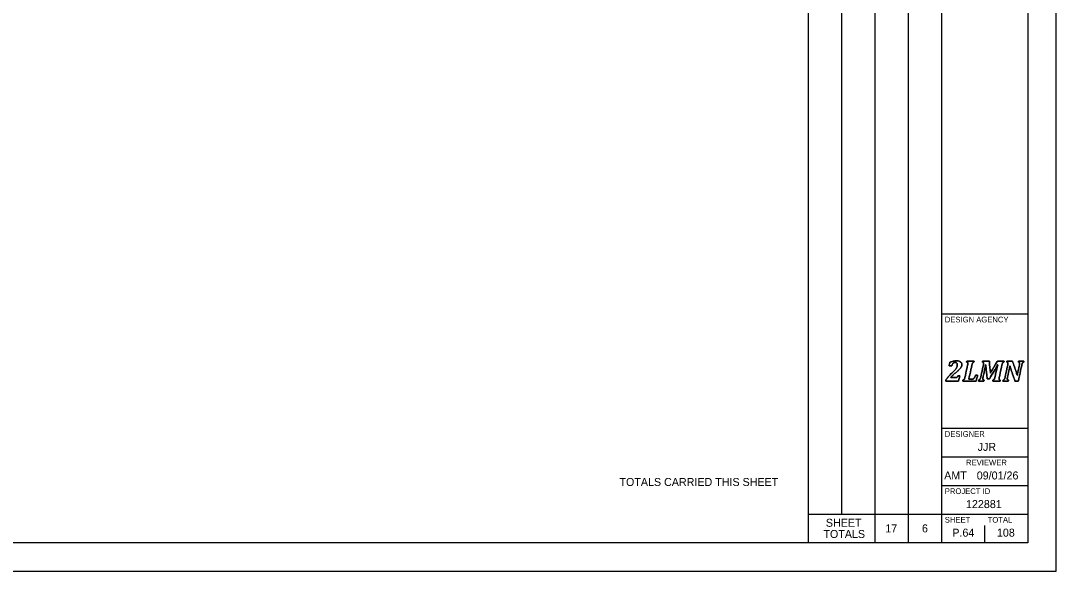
# Model space of a CAD drawing. Extents: x -32 to 34, y 0 to 22.
# Drawn here: x 15.89 to 34, y 0 to 9.62 of the extents above; entities that cross this region are included whole.
import ezdxf

# ---------------------------------------------------------------- set-up
doc = ezdxf.new("R2010")
doc.units = 0
for name, color, linetype in [('SH_Border', 7, 'Continuous'), ('SH_Cut_Line', 7, 'Continuous'), ('SH_Data', 7, 'Continuous'), ('SH_Major_Grid_Line', 7, 'Continuous'), ('SH_Text', 7, 'Continuous')]:
    doc.layers.add(name, color=color, linetype=linetype)

msp = doc.modelspace()

# ---------------------------------------------------------------- linework, layer by layer
at = {"layer": 'SH_Border'}
for p, q in [((32, 0.5), (32, 21.5)), ((32, 4.5), (33.5, 4.5)), ((32, 2.5), (33.5, 2.5)), ((32, 2), (33.5, 2)), ((32, 1.5), (33.5, 1.5)), ((32, 1), (33.5, 1))]:
    msp.add_line(p, q, dxfattribs=at)
msp.add_lwpolyline([(1.5, 21.5), (33.5, 21.5), (33.5, 0.5), (1.5, 0.5)], close=True, dxfattribs=at)
at = {"layer": 'SH_Cut_Line'}
msp.add_lwpolyline([(0, 0), (34, 0), (34, 22), (0, 22)], close=True, dxfattribs=at)
at = {"layer": 'SH_Data'}
for p, q in [((29.666, 0.5), (29.666, 21.5)), ((30.833, 0.5), (30.833, 21.5)), ((30.25, 1), (30.25, 21.25)), ((31.417, 0.5), (31.417, 21.25)), ((32.75, 3.5), (32.75, 3.5)), ((29.666, 1), (32, 1)), ((29.958, 0.75), (29.958, 0.75)), ((30.542, 0.75), (30.542, 0.75)), ((31.125, 0.75), (31.125, 0.75)), ((31.708, 0.75), (31.708, 0.75)), ((32.75, 0.5), (32.75, 0.8)), ((32.375, 0.675), (32.375, 0.675))]:
    msp.add_line(p, q, dxfattribs=at)
for points in [[(32.237, 3.388), (32.246, 3.388), (32.253, 3.389), (32.258, 3.39), (32.263, 3.392), (32.267, 3.394), (32.27, 3.397), (32.273, 3.401), (32.277, 3.408), (32.281, 3.417), (32.281, 3.417), (32.312, 3.417), (32.312, 3.417), (32.312, 3.417), (32.29, 3.326), (32.29, 3.326), (32.29, 3.326), (32.066, 3.326), (32.066, 3.326), (32.066, 3.326), (32.069, 3.343), (32.069, 3.343), (32.078, 3.358), (32.091, 3.375), (32.106, 3.394), (32.122, 3.412), (32.144, 3.435), (32.172, 3.462), (32.197, 3.486), (32.217, 3.506), (32.23, 3.521), (32.243, 3.537), (32.253, 3.551), (32.259, 3.566), (32.266, 3.58), (32.269, 3.595), (32.269, 3.61), (32.269, 3.622), (32.266, 3.632), (32.26, 3.64), (32.253, 3.647), (32.245, 3.65), (32.234, 3.65), (32.22, 3.65), (32.208, 3.646), (32.198, 3.636), (32.188, 3.627), (32.18, 3.613), (32.172, 3.593), (32.172, 3.593), (32.126, 3.593), (32.126, 3.593), (32.126, 3.593), (32.14, 3.654), (32.14, 3.654), (32.166, 3.663), (32.188, 3.669), (32.205, 3.673), (32.223, 3.676), (32.24, 3.678), (32.258, 3.678), (32.278, 3.678), (32.295, 3.675), (32.309, 3.669), (32.322, 3.664), (32.332, 3.656), (32.339, 3.646), (32.345, 3.637), (32.348, 3.626), (32.348, 3.613), (32.348, 3.602), (32.346, 3.591), (32.342, 3.581), (32.339, 3.571), (32.333, 3.56), (32.324, 3.549), (32.315, 3.539), (32.304, 3.526), (32.289, 3.513), (32.275, 3.499), (32.254, 3.482), (32.228, 3.46), (32.216, 3.45), (32.202, 3.438), (32.188, 3.425), (32.174, 3.412), (32.162, 3.4), (32.154, 3.391), (32.154, 3.391), (32.153, 3.388), (32.153, 3.388), (32.153, 3.388), (32.237, 3.388), (32.237, 3.388)], [(32.237, 3.388), (32.237, 3.388), (32.153, 3.388), (32.153, 3.388), (32.153, 3.388), (32.154, 3.391), (32.154, 3.391), (32.162, 3.4), (32.174, 3.412), (32.188, 3.425), (32.202, 3.438), (32.216, 3.45), (32.228, 3.46), (32.254, 3.482), (32.275, 3.499), (32.289, 3.513), (32.304, 3.526), (32.315, 3.539), (32.324, 3.549), (32.333, 3.56), (32.339, 3.571), (32.342, 3.581), (32.346, 3.591), (32.348, 3.602), (32.348, 3.613), (32.348, 3.626), (32.345, 3.637), (32.339, 3.646), (32.332, 3.656), (32.322, 3.664), (32.309, 3.669), (32.295, 3.675), (32.278, 3.678), (32.258, 3.678), (32.24, 3.678), (32.223, 3.676), (32.205, 3.673), (32.188, 3.669), (32.166, 3.663), (32.14, 3.654), (32.14, 3.654), (32.126, 3.593), (32.126, 3.593), (32.126, 3.593), (32.172, 3.593), (32.172, 3.593), (32.18, 3.613), (32.188, 3.627), (32.198, 3.636), (32.208, 3.646), (32.22, 3.65), (32.234, 3.65), (32.245, 3.65), (32.253, 3.647), (32.26, 3.64), (32.266, 3.632), (32.269, 3.622), (32.269, 3.61), (32.269, 3.595), (32.266, 3.58), (32.259, 3.566), (32.253, 3.551), (32.243, 3.537), (32.23, 3.521), (32.217, 3.506), (32.197, 3.486), (32.172, 3.462), (32.144, 3.435), (32.122, 3.412), (32.106, 3.394), (32.091, 3.375), (32.078, 3.358), (32.069, 3.343), (32.069, 3.343), (32.066, 3.326), (32.066, 3.326), (32.066, 3.326), (32.29, 3.326), (32.29, 3.326), (32.29, 3.326), (32.312, 3.417), (32.312, 3.417), (32.312, 3.417), (32.281, 3.417), (32.281, 3.417), (32.277, 3.408), (32.273, 3.401), (32.27, 3.397), (32.267, 3.394), (32.263, 3.392), (32.258, 3.39), (32.253, 3.389), (32.246, 3.388), (32.237, 3.388)], [(32.518, 3.356), (32.527, 3.356), (32.533, 3.357), (32.538, 3.358), (32.542, 3.36), (32.546, 3.362), (32.55, 3.365), (32.554, 3.368), (32.558, 3.372), (32.562, 3.377), (32.567, 3.382), (32.571, 3.388), (32.576, 3.397), (32.58, 3.405), (32.585, 3.415), (32.589, 3.427), (32.589, 3.427), (32.624, 3.427), (32.624, 3.427), (32.624, 3.427), (32.598, 3.326), (32.598, 3.326), (32.598, 3.326), (32.365, 3.326), (32.365, 3.326), (32.365, 3.326), (32.369, 3.343), (32.369, 3.343), (32.376, 3.345), (32.381, 3.348), (32.385, 3.351), (32.389, 3.355), (32.392, 3.36), (32.395, 3.366), (32.398, 3.373), (32.4, 3.382), (32.403, 3.395), (32.403, 3.395), (32.449, 3.605), (32.449, 3.605), (32.452, 3.615), (32.453, 3.625), (32.453, 3.635), (32.453, 3.642), (32.451, 3.647), (32.448, 3.651), (32.444, 3.654), (32.439, 3.656), (32.432, 3.657), (32.432, 3.657), (32.435, 3.674), (32.435, 3.674), (32.435, 3.674), (32.563, 3.674), (32.563, 3.674), (32.563, 3.674), (32.559, 3.657), (32.559, 3.657), (32.552, 3.655), (32.547, 3.652), (32.543, 3.649), (32.539, 3.645), (32.536, 3.64), (32.533, 3.634), (32.531, 3.627), (32.528, 3.618), (32.525, 3.605), (32.525, 3.605), (32.47, 3.356), (32.47, 3.356), (32.47, 3.356), (32.518, 3.356), (32.518, 3.356)], [(32.518, 3.356), (32.518, 3.356), (32.47, 3.356), (32.47, 3.356), (32.47, 3.356), (32.525, 3.605), (32.525, 3.605), (32.528, 3.618), (32.531, 3.627), (32.533, 3.634), (32.536, 3.64), (32.539, 3.645), (32.543, 3.649), (32.547, 3.652), (32.552, 3.655), (32.559, 3.657), (32.559, 3.657), (32.563, 3.674), (32.563, 3.674), (32.563, 3.674), (32.435, 3.674), (32.435, 3.674), (32.435, 3.674), (32.432, 3.657), (32.432, 3.657), (32.439, 3.656), (32.444, 3.654), (32.448, 3.651), (32.451, 3.647), (32.453, 3.642), (32.453, 3.635), (32.453, 3.625), (32.452, 3.615), (32.449, 3.605), (32.449, 3.605), (32.403, 3.395), (32.403, 3.395), (32.4, 3.382), (32.398, 3.373), (32.395, 3.366), (32.392, 3.36), (32.389, 3.355), (32.385, 3.351), (32.381, 3.348), (32.376, 3.345), (32.369, 3.343), (32.369, 3.343), (32.365, 3.326), (32.365, 3.326), (32.365, 3.326), (32.598, 3.326), (32.598, 3.326), (32.598, 3.326), (32.624, 3.427), (32.624, 3.427), (32.624, 3.427), (32.589, 3.427), (32.589, 3.427), (32.585, 3.415), (32.58, 3.405), (32.576, 3.397), (32.571, 3.388), (32.567, 3.382), (32.562, 3.377), (32.558, 3.372), (32.554, 3.368), (32.55, 3.365), (32.546, 3.362), (32.542, 3.36), (32.538, 3.358), (32.533, 3.357), (32.527, 3.356), (32.518, 3.356)], [(32.829, 3.674), (32.829, 3.674), (32.849, 3.461), (32.849, 3.461), (32.849, 3.461), (32.969, 3.674), (32.969, 3.674), (32.969, 3.674), (33.087, 3.674), (33.087, 3.674), (33.087, 3.674), (33.084, 3.657), (33.084, 3.657), (33.077, 3.655), (33.071, 3.652), (33.067, 3.649), (33.064, 3.645), (33.06, 3.64), (33.058, 3.634), (33.055, 3.627), (33.052, 3.618), (33.05, 3.605), (33.05, 3.605), (33.003, 3.395), (33.003, 3.395), (33.002, 3.39), (33.002, 3.387), (33.001, 3.384), (33.001, 3.382), (33.001, 3.379), (33, 3.376), (33, 3.373), (33, 3.369), (33, 3.365), (33, 3.358), (33.002, 3.353), (33.005, 3.349), (33.008, 3.346), (33.014, 3.344), (33.021, 3.343), (33.021, 3.343), (33.018, 3.326), (33.018, 3.326), (33.018, 3.326), (32.89, 3.326), (32.89, 3.326), (32.89, 3.326), (32.893, 3.343), (32.893, 3.343), (32.9, 3.345), (32.906, 3.348), (32.91, 3.351), (32.914, 3.355), (32.917, 3.36), (32.919, 3.366), (32.922, 3.373), (32.925, 3.382), (32.928, 3.395), (32.928, 3.395), (32.951, 3.502), (32.951, 3.502), (32.954, 3.513), (32.957, 3.529), (32.962, 3.548), (32.967, 3.568), (32.972, 3.588), (32.978, 3.609), (32.978, 3.609), (32.973, 3.609), (32.973, 3.609), (32.965, 3.594), (32.957, 3.579), (32.948, 3.563), (32.948, 3.563), (32.833, 3.364), (32.833, 3.364), (32.833, 3.364), (32.792, 3.364), (32.792, 3.364), (32.792, 3.364), (32.775, 3.518), (32.775, 3.518), (32.773, 3.537), (32.772, 3.554), (32.77, 3.569), (32.769, 3.583), (32.768, 3.597), (32.768, 3.611), (32.768, 3.611), (32.764, 3.611), (32.764, 3.611), (32.761, 3.596), (32.758, 3.578), (32.755, 3.558), (32.751, 3.538), (32.747, 3.521), (32.744, 3.507), (32.744, 3.507), (32.72, 3.395), (32.72, 3.395), (32.719, 3.39), (32.718, 3.387), (32.718, 3.384), (32.717, 3.382), (32.717, 3.379), (32.717, 3.376), (32.717, 3.373), (32.716, 3.369), (32.716, 3.365), (32.716, 3.358), (32.718, 3.353), (32.721, 3.349), (32.725, 3.346), (32.73, 3.344), (32.738, 3.343), (32.738, 3.343), (32.734, 3.326), (32.734, 3.326), (32.734, 3.326), (32.641, 3.326), (32.641, 3.326), (32.641, 3.326), (32.644, 3.343), (32.644, 3.343), (32.651, 3.345), (32.657, 3.348), (32.661, 3.351), (32.665, 3.355), (32.668, 3.36), (32.67, 3.366), (32.673, 3.373), (32.676, 3.382), (32.679, 3.395), (32.679, 3.395), (32.725, 3.605), (32.725, 3.605), (32.727, 3.615), (32.728, 3.625), (32.728, 3.635), (32.728, 3.642), (32.727, 3.647), (32.723, 3.651), (32.72, 3.654), (32.715, 3.656), (32.707, 3.657), (32.707, 3.657), (32.711, 3.674), (32.711, 3.674), (32.711, 3.674), (32.829, 3.674), (32.829, 3.674)], [(32.829, 3.674), (32.829, 3.674), (32.711, 3.674), (32.711, 3.674), (32.711, 3.674), (32.707, 3.657), (32.707, 3.657), (32.715, 3.656), (32.72, 3.654), (32.723, 3.651), (32.727, 3.647), (32.728, 3.642), (32.728, 3.635), (32.728, 3.625), (32.727, 3.615), (32.725, 3.605), (32.725, 3.605), (32.679, 3.395), (32.679, 3.395), (32.676, 3.382), (32.673, 3.373), (32.67, 3.366), (32.668, 3.36), (32.665, 3.355), (32.661, 3.351), (32.657, 3.348), (32.651, 3.345), (32.644, 3.343), (32.644, 3.343), (32.641, 3.326), (32.641, 3.326), (32.641, 3.326), (32.734, 3.326), (32.734, 3.326), (32.734, 3.326), (32.738, 3.343), (32.738, 3.343), (32.73, 3.344), (32.725, 3.346), (32.721, 3.349), (32.718, 3.353), (32.716, 3.358), (32.716, 3.365), (32.716, 3.369), (32.717, 3.373), (32.717, 3.376), (32.717, 3.379), (32.717, 3.382), (32.718, 3.384), (32.718, 3.387), (32.719, 3.39), (32.72, 3.395), (32.72, 3.395), (32.744, 3.507), (32.744, 3.507), (32.747, 3.521), (32.751, 3.538), (32.755, 3.558), (32.758, 3.578), (32.761, 3.596), (32.764, 3.611), (32.764, 3.611), (32.768, 3.611), (32.768, 3.611), (32.768, 3.597), (32.769, 3.583), (32.77, 3.569), (32.772, 3.554), (32.773, 3.537), (32.775, 3.518), (32.775, 3.518), (32.792, 3.364), (32.792, 3.364), (32.792, 3.364), (32.833, 3.364), (32.833, 3.364), (32.833, 3.364), (32.948, 3.563), (32.948, 3.563), (32.957, 3.579), (32.965, 3.594), (32.973, 3.609), (32.973, 3.609), (32.978, 3.609), (32.978, 3.609), (32.972, 3.588), (32.967, 3.568), (32.962, 3.548), (32.957, 3.529), (32.954, 3.513), (32.951, 3.502), (32.951, 3.502), (32.928, 3.395), (32.928, 3.395), (32.925, 3.382), (32.922, 3.373), (32.919, 3.366), (32.917, 3.36), (32.914, 3.355), (32.91, 3.351), (32.906, 3.348), (32.9, 3.345), (32.893, 3.343), (32.893, 3.343), (32.89, 3.326), (32.89, 3.326), (32.89, 3.326), (33.018, 3.326), (33.018, 3.326), (33.018, 3.326), (33.021, 3.343), (33.021, 3.343), (33.014, 3.344), (33.008, 3.346), (33.005, 3.349), (33.002, 3.353), (33, 3.358), (33, 3.365), (33, 3.369), (33, 3.373), (33, 3.376), (33.001, 3.379), (33.001, 3.382), (33.001, 3.384), (33.002, 3.387), (33.002, 3.39), (33.003, 3.395), (33.003, 3.395), (33.05, 3.605), (33.05, 3.605), (33.052, 3.618), (33.055, 3.627), (33.058, 3.634), (33.06, 3.64), (33.064, 3.645), (33.067, 3.649), (33.071, 3.652), (33.077, 3.655), (33.084, 3.657), (33.084, 3.657), (33.087, 3.674), (33.087, 3.674), (33.087, 3.674), (32.969, 3.674), (32.969, 3.674), (32.969, 3.674), (32.849, 3.461), (32.849, 3.461), (32.849, 3.461), (32.829, 3.674), (32.829, 3.674)], [(33.137, 3.674), (33.137, 3.674), (33.234, 3.674), (33.234, 3.674), (33.234, 3.674), (33.283, 3.53), (33.283, 3.53), (33.296, 3.49), (33.307, 3.456), (33.315, 3.426), (33.315, 3.426), (33.318, 3.426), (33.318, 3.426), (33.323, 3.455), (33.329, 3.488), (33.337, 3.523), (33.337, 3.523), (33.355, 3.605), (33.355, 3.605), (33.357, 3.615), (33.358, 3.625), (33.358, 3.635), (33.358, 3.642), (33.357, 3.647), (33.353, 3.651), (33.35, 3.654), (33.345, 3.656), (33.337, 3.657), (33.337, 3.657), (33.341, 3.674), (33.341, 3.674), (33.341, 3.674), (33.434, 3.674), (33.434, 3.674), (33.434, 3.674), (33.431, 3.657), (33.431, 3.657), (33.424, 3.655), (33.418, 3.652), (33.414, 3.649), (33.41, 3.645), (33.407, 3.64), (33.405, 3.634), (33.402, 3.627), (33.399, 3.618), (33.396, 3.605), (33.396, 3.605), (33.335, 3.326), (33.335, 3.326), (33.335, 3.326), (33.277, 3.326), (33.277, 3.326), (33.277, 3.326), (33.216, 3.504), (33.216, 3.504), (33.211, 3.518), (33.207, 3.531), (33.204, 3.543), (33.2, 3.556), (33.195, 3.571), (33.19, 3.59), (33.19, 3.59), (33.186, 3.59), (33.186, 3.59), (33.185, 3.579), (33.182, 3.563), (33.179, 3.543), (33.175, 3.523), (33.17, 3.501), (33.165, 3.478), (33.165, 3.478), (33.147, 3.395), (33.147, 3.395), (33.146, 3.39), (33.145, 3.387), (33.145, 3.384), (33.144, 3.382), (33.144, 3.379), (33.144, 3.376), (33.143, 3.373), (33.143, 3.369), (33.143, 3.365), (33.143, 3.358), (33.145, 3.353), (33.148, 3.349), (33.152, 3.346), (33.157, 3.344), (33.164, 3.343), (33.164, 3.343), (33.161, 3.326), (33.161, 3.326), (33.161, 3.326), (33.067, 3.326), (33.067, 3.326), (33.067, 3.326), (33.071, 3.343), (33.071, 3.343), (33.078, 3.345), (33.083, 3.348), (33.087, 3.351), (33.091, 3.355), (33.094, 3.36), (33.097, 3.366), (33.1, 3.373), (33.102, 3.382), (33.105, 3.395), (33.105, 3.395), (33.151, 3.605), (33.151, 3.605), (33.154, 3.615), (33.155, 3.625), (33.155, 3.635), (33.155, 3.642), (33.153, 3.647), (33.15, 3.651), (33.146, 3.654), (33.141, 3.656), (33.134, 3.657), (33.134, 3.657), (33.137, 3.674), (33.137, 3.674)], [(33.137, 3.674), (33.137, 3.674), (33.134, 3.657), (33.134, 3.657), (33.141, 3.656), (33.146, 3.654), (33.15, 3.651), (33.153, 3.647), (33.155, 3.642), (33.155, 3.635), (33.155, 3.625), (33.154, 3.615), (33.151, 3.605), (33.151, 3.605), (33.105, 3.395), (33.105, 3.395), (33.102, 3.382), (33.1, 3.373), (33.097, 3.366), (33.094, 3.36), (33.091, 3.355), (33.087, 3.351), (33.083, 3.348), (33.078, 3.345), (33.071, 3.343), (33.071, 3.343), (33.067, 3.326), (33.067, 3.326), (33.067, 3.326), (33.161, 3.326), (33.161, 3.326), (33.161, 3.326), (33.164, 3.343), (33.164, 3.343), (33.157, 3.344), (33.152, 3.346), (33.148, 3.349), (33.145, 3.353), (33.143, 3.358), (33.143, 3.365), (33.143, 3.369), (33.143, 3.373), (33.144, 3.376), (33.144, 3.379), (33.144, 3.382), (33.145, 3.384), (33.145, 3.387), (33.146, 3.39), (33.147, 3.395), (33.147, 3.395), (33.165, 3.478), (33.165, 3.478), (33.17, 3.501), (33.175, 3.523), (33.179, 3.543), (33.182, 3.563), (33.185, 3.579), (33.186, 3.59), (33.186, 3.59), (33.19, 3.59), (33.19, 3.59), (33.195, 3.571), (33.2, 3.556), (33.204, 3.543), (33.207, 3.531), (33.211, 3.518), (33.216, 3.504), (33.216, 3.504), (33.277, 3.326), (33.277, 3.326), (33.277, 3.326), (33.335, 3.326), (33.335, 3.326), (33.335, 3.326), (33.396, 3.605), (33.396, 3.605), (33.399, 3.618), (33.402, 3.627), (33.405, 3.634), (33.407, 3.64), (33.41, 3.645), (33.414, 3.649), (33.418, 3.652), (33.424, 3.655), (33.431, 3.657), (33.431, 3.657), (33.434, 3.674), (33.434, 3.674), (33.434, 3.674), (33.341, 3.674), (33.341, 3.674), (33.341, 3.674), (33.337, 3.657), (33.337, 3.657), (33.345, 3.656), (33.35, 3.654), (33.353, 3.651), (33.357, 3.647), (33.358, 3.642), (33.358, 3.635), (33.358, 3.625), (33.357, 3.615), (33.355, 3.605), (33.355, 3.605), (33.337, 3.523), (33.337, 3.523), (33.329, 3.488), (33.323, 3.455), (33.318, 3.426), (33.318, 3.426), (33.315, 3.426), (33.315, 3.426), (33.307, 3.456), (33.296, 3.49), (33.283, 3.53), (33.283, 3.53), (33.234, 3.674), (33.234, 3.674), (33.234, 3.674), (33.137, 3.674), (33.137, 3.674)]]:
    msp.add_open_spline(points, degree=3, dxfattribs=at)

# ---------------------------------------------------------------- texts
for s, height, p in [('DESIGN AGENCY', 0.1, (32.05, 4.35)), ('DESIGNER', 0.1, (32.05, 2.35)), ('JJR', 0.14, (32.624, 2.105)), ('REVIEWER', 0.1, (32.422, 1.85)), ('AMT', 0.14, (32.039, 1.605)), ('09/01/26', 0.14, (32.609, 1.605)), ('PROJECT ID', 0.1, (32.05, 1.35)), ('122881', 0.14, (32.421, 1.105)), ('SHEET', 0.14, (29.97, 0.778)), ('SHEET', 0.1, (32.05, 0.85)), ('TOTAL', 0.1, (32.8, 0.85)), ('P.64', 0.14, (32.182, 0.605)), ('108', 0.14, (32.962, 0.605)), ('TOTALS', 0.14, (29.927, 0.582))]:
    msp.add_text(s, height=height, dxfattribs=at).set_placement(p)
at = {"layer": 'SH_Major_Grid_Line'}
msp.add_text('TOTALS CARRIED THIS SHEET', height=0.14, dxfattribs=at).set_placement((26.36, 1.491))
at = {"layer": 'SH_Text'}
for s, p in [('17', (31.009, 0.68)), ('6', (31.651, 0.68))]:
    msp.add_text(s, height=0.14, dxfattribs=at).set_placement(p)

doc.saveas('drawing.dxf')
